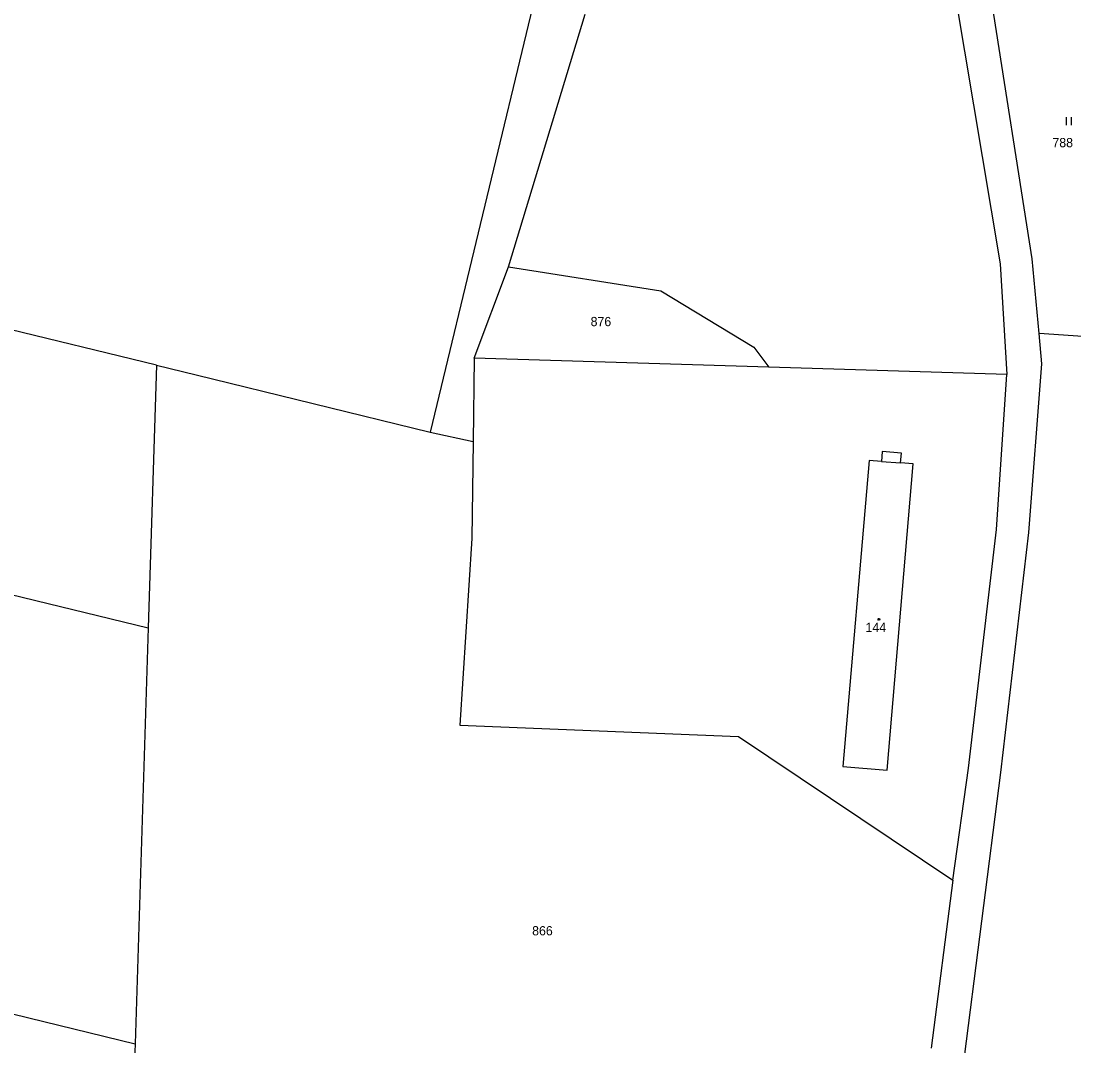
# Model space of a CAD drawing. Extents: x -812394 to -807601, y -1013097 to -1009266.
# Drawn here: x -809612.2 to -809418.3, y -1010590.6 to -1010401.8 of the extents above; entities that cross this region are included whole.
import ezdxf

# ---------------------------------------------------------------- set-up
doc = ezdxf.new("R2010")
doc.units = 0
for name, color, linetype in [('Default', 7, 'Continuous'), ('KN_HRANICE', 7, 'Continuous'), ('KN_KULTURY', 7, 'Continuous'), ('KN_PARCELY', 7, 'Continuous'), ('KN_SLUCKY', 7, 'Continuous')]:
    doc.layers.add(name, color=color, linetype=linetype)

# ---------------------------------------------------------------- blocks, each defined once
blk = doc.blocks.new('306')
at = {"layer": 'Default'}
for p, q in [((-0.5, 1.5), (-0.5, 0)), ((0.5, 0), (0.5, 1.5))]:
    blk.add_line(p, q, dxfattribs=at)
blk = doc.blocks.new('402')
at = {"layer": 'Default'}
blk.add_lwpolyline([(0.09, 0.15), (0.18, 0), (0.09, -0.15), (-0.09, -0.15), (-0.18, 0), (-0.09, 0.15), (0.09, 0.15)], dxfattribs=at)

msp = doc.modelspace()

# ---------------------------------------------------------------- linework, layer by layer
at = {"layer": 'KN_HRANICE'}
for p, q in [((-809450.65, -1010334.75), (-809431.9, -1010446.55)), ((-809425.97, -1010445.61), (-809436.85, -1010376.65)), ((-809514.24, -1010383.44), (-809536.89, -1010477.53)), ((-809522.42, -1010447.11), (-809508.32, -1010400.6)), ((-809587.27, -1010465.23), (-809714.42, -1010434.16)), ((-809528.75, -1010463.9), (-809522.42, -1010447.11)), ((-809522.42, -1010447.11), (-809494.36, -1010451.5)), ((-809431.9, -1010446.55), (-809430.67, -1010466.91)), ((-809424.72, -1010459.4), (-809425.97, -1010445.61)), ((-809494.36, -1010451.5), (-809477.25, -1010461.87)), ((-809416.64, -1010459.93), (-809424.72, -1010459.4)), ((-809424.21, -1010464.95), (-809424.72, -1010459.4)), ((-809477.25, -1010461.87), (-809474.49, -1010465.57)), ((-809528.75, -1010463.9), (-809528.97, -1010479.27)), ((-809474.49, -1010465.57), (-809528.75, -1010463.9)), ((-809587.27, -1010465.23), (-809588.81, -1010513.56)), ((-809587.27, -1010465.23), (-809580, -1010467)), ((-809430.67, -1010466.91), (-809474.49, -1010465.57)), ((-809426.59, -1010496.04), (-809424.21, -1010464.95)), ((-809580, -1010467), (-809536.89, -1010477.53)), ((-809536.89, -1010477.53), (-809528.97, -1010479.27)), ((-809731.16, -1010478.93), (-809588.81, -1010513.56)), ((-809528.97, -1010479.27), (-809529.22, -1010497.13)), ((-809529.22, -1010497.13), (-809531.43, -1010531.51)), ((-809431.77, -1010540.21), (-809426.59, -1010496.04)), ((-809588.81, -1010513.56), (-809591.24, -1010590.16)), ((-809531.43, -1010531.51), (-809480.06, -1010533.57)), ((-809480.06, -1010533.57), (-809440.59, -1010560.03)), ((-809445.19, -1010645.2), (-809431.77, -1010540.21)), ((-809731.49, -1010556.03), (-809591.24, -1010590.16)), ((-809440.59, -1010560.03), (-809444.6, -1010590.99)), ((-809591.24, -1010590.16), (-809591.38, -1010594.61))]:
    msp.add_line(p, q, dxfattribs=at)
msp.add_lwpolyline([(-809440.59, -1010560.03), (-809437.72, -1010539.45), (-809432.57, -1010495.49), (-809430.67, -1010466.91)], dxfattribs=at)
at = {"layer": 'KN_SLUCKY'}
msp.add_line((-809453.74, -1010482.93), (-809450.22, -1010483.22), dxfattribs=at)
for points in [[(-809450.22, -1010483.22), (-809450.07, -1010481.4), (-809453.59, -1010481.09), (-809453.74, -1010482.93)], [(-809453.74, -1010482.93), (-809456, -1010482.74), (-809460.85, -1010539.12)], [(-809460.85, -1010539.12), (-809452.7, -1010539.8), (-809447.88, -1010483.41), (-809450.22, -1010483.22)]]:
    msp.add_lwpolyline(points, dxfattribs=at)

# ---------------------------------------------------------------- block references
at = {"layer": 'KN_KULTURY'}
for name, p in [('306', (-809419.22, -1010421.03)), ('402', (-809454.22, -1010512))]:
    msp.add_blockref(name, p, dxfattribs=at)

# ---------------------------------------------------------------- texts
at = {"layer": 'KN_PARCELY'}
for s, p in [('788', (-809422.26, -1010425.08)), ('876', (-809507.32, -1010458.03)), ('144', (-809456.68, -1010514.34)), ('866', (-809518.09, -1010570.21))]:
    msp.add_text(s, height=1.7, dxfattribs=at).set_placement(p)

doc.saveas('drawing.dxf')
